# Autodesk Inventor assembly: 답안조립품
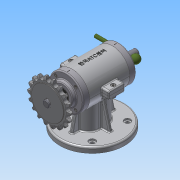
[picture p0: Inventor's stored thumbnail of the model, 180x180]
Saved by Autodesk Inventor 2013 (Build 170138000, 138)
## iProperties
Created: 2016-04
Part Number: 답안조립품
Document SubType Name: Assembly
Designer: Administrator
Mass: 1745.71 g
Surface Area: 1440.69 cm^2
Volume: 462.009 cm^3
Density: 3.77852 g/cm^3
Author: Administrator
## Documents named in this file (19)
- C:\Users\Administrator\Desktop\360408V1001\답안조립품.iam
- C:\Users\Administrator\Desktop\360408V1001\본체.ipt
- C:\Users\Administrator\Desktop\360408V1001\너트 M4.ipt
- C:\Users\Administrator\Desktop\360408V1001\뒤커버.ipt
- C:\Users\Administrator\Desktop\360408V1001\레바.ipt
- C:\Users\Administrator\Desktop\360408V1001\멈춤나사 M3x8.ipt
- C:\Users\Administrator\Desktop\360408V1001\베어링 6201.ipt
- C:\Users\Administrator\Desktop\360408V1001\베어링 6202.ipt
- C:\Users\Administrator\Desktop\360408V1001\본체상부커버.ipt
- C:\Users\Administrator\Desktop\360408V1001\볼트 M3x0.5x8.ipt
- C:\Users\Administrator\Desktop\360408V1001\볼트 M4 x 16.ipt
- C:\Users\Administrator\Desktop\360408V1001\스프로킷.ipt
- C:\Users\Administrator\Desktop\360408V1001\스프링.ipt
- C:\Users\Administrator\Desktop\360408V1001\슬라이드.ipt
- C:\Users\Administrator\Desktop\360408V1001\앞커버.ipt
- C:\Users\Administrator\Desktop\360408V1001\오일실 12 22 7.ipt
- C:\Users\Administrator\Desktop\360408V1001\와셔 ST 4-100.ipt
- C:\Users\Administrator\Desktop\360408V1001\키 4 x 4 x 18.ipt
- C:\Users\Administrator\Desktop\360408V1001\편심축.ipt
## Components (6 placed, 3 different names)
1. ISO 4032 M4:1
2. ISO 4762 M4 x 16:1
3. ISO 7091 ST 4 - 100 HV:1
4. ISO 4762 M4 x 16:2
5. ISO 7091 ST 4 - 100 HV:2
6. ISO 4032 M4:2
